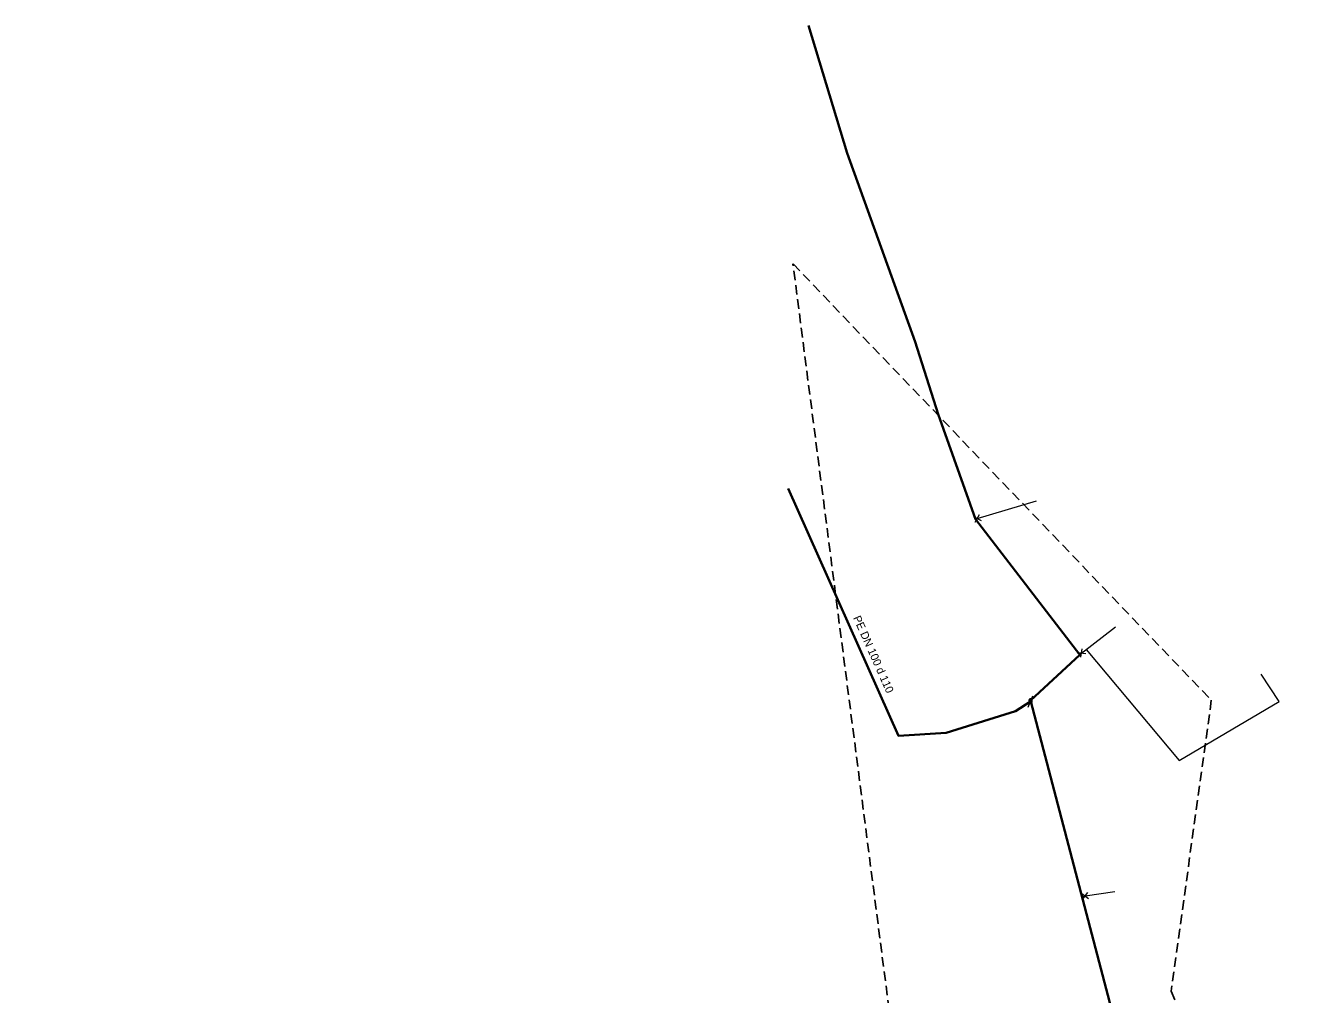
# Model space of a CAD drawing. Extents: x -743677 to -742923, y -1027084 to -1026416.
# Drawn here: x -743300.4 to -743108.7, y -1026561.5 to -1026416.4 of the extents above; entities that cross this region are included whole.
import ezdxf

# ---------------------------------------------------------------- set-up
doc = ezdxf.new("R2010")
doc.units = 0
doc.header["$LTSCALE"] = 0.48
doc.linetypes.add('MEDIUM_DASHED', pattern=[4.5, 3, -1.5])
for name, color, linetype, lineweight in [('15', 7, 'Continuous', 13), ('16', 7, 'Continuous', 35), ('59', 7, 'Continuous', 13), ('62', 7, 'MEDIUM_DASHED', 25)]:
    doc.layers.add(name, color=color, linetype=linetype, lineweight=lineweight)
doc.layers.add('17', color=7, linetype='Continuous')

msp = doc.modelspace()

# ---------------------------------------------------------------- linework, layer by layer
at = {"layer": '15'}
for p, q in [((-743158.264, -1026489.932), (-743157.131, -1026490.55)), ((-743158.008, -1026490.81), (-743157.387, -1026489.666)), ((-743142.718, -1026510.317), (-743141.438, -1026510.484)), ((-743142.162, -1026511.044), (-743141.997, -1026509.752)), ((-743150.054, -1026518.519), (-743149.357, -1026516.793)), ((-743142.045, -1026546.414), (-743141.012, -1026547.188)), ((-743141.918, -1026547.32), (-743141.14, -1026546.276))]:
    msp.add_line(p, q, dxfattribs=at)
for points in [[(-743149.495, -1026517.493), (-743149.502, -1026517.441), (-743149.519, -1026517.391), (-743149.548, -1026517.347), (-743149.585, -1026517.31), (-743149.63, -1026517.283), (-743149.679, -1026517.266), (-743149.733, -1026517.262), (-743149.784, -1026517.269), (-743149.833, -1026517.288), (-743149.877, -1026517.317), (-743149.913, -1026517.356), (-743149.939, -1026517.401), (-743149.955, -1026517.452), (-743149.958, -1026517.504), (-743149.95, -1026517.556), (-743149.929, -1026517.605), (-743149.899, -1026517.648), (-743149.86, -1026517.682), (-743149.814, -1026517.708), (-743149.762, -1026517.722), (-743149.71, -1026517.724), (-743149.659, -1026517.714), (-743149.61, -1026517.693), (-743149.568, -1026517.662), (-743149.534, -1026517.621), (-743149.51, -1026517.575), (-743149.497, -1026517.524)], [(-743149.526, -1026517.493), (-743149.532, -1026517.444), (-743149.549, -1026517.398), (-743149.576, -1026517.358), (-743149.614, -1026517.326), (-743149.657, -1026517.304), (-743149.706, -1026517.293), (-743149.755, -1026517.293), (-743149.801, -1026517.306), (-743149.845, -1026517.33), (-743149.88, -1026517.363), (-743149.907, -1026517.404), (-743149.924, -1026517.451), (-743149.928, -1026517.5), (-743149.921, -1026517.548), (-743149.902, -1026517.593), (-743149.872, -1026517.633), (-743149.833, -1026517.664), (-743149.789, -1026517.684), (-743149.742, -1026517.694), (-743149.693, -1026517.692), (-743149.646, -1026517.677), (-743149.603, -1026517.652), (-743149.568, -1026517.618), (-743149.543, -1026517.576), (-743149.529, -1026517.529)], [(-743149.458, -1026517.647), (-743149.464, -1026517.595), (-743149.481, -1026517.545), (-743149.51, -1026517.501), (-743149.547, -1026517.464), (-743149.592, -1026517.437), (-743149.642, -1026517.42), (-743149.695, -1026517.416), (-743149.747, -1026517.423), (-743149.796, -1026517.442), (-743149.839, -1026517.471), (-743149.875, -1026517.51), (-743149.901, -1026517.555), (-743149.917, -1026517.606), (-743149.92, -1026517.658), (-743149.912, -1026517.71), (-743149.892, -1026517.759), (-743149.861, -1026517.802), (-743149.822, -1026517.836), (-743149.776, -1026517.862), (-743149.725, -1026517.876), (-743149.672, -1026517.878), (-743149.621, -1026517.868), (-743149.573, -1026517.847), (-743149.53, -1026517.816), (-743149.496, -1026517.775), (-743149.472, -1026517.729), (-743149.46, -1026517.678)], [(-743149.556, -1026517.493), (-743149.561, -1026517.448), (-743149.578, -1026517.406), (-743149.607, -1026517.371), (-743149.642, -1026517.344), (-743149.684, -1026517.327), (-743149.73, -1026517.322), (-743149.774, -1026517.328), (-743149.816, -1026517.347), (-743149.85, -1026517.375), (-743149.877, -1026517.412), (-743149.894, -1026517.454), (-743149.897, -1026517.499), (-743149.891, -1026517.544), (-743149.872, -1026517.585), (-743149.843, -1026517.619), (-743149.806, -1026517.645), (-743149.762, -1026517.661), (-743149.718, -1026517.664), (-743149.673, -1026517.656), (-743149.632, -1026517.636), (-743149.598, -1026517.607), (-743149.573, -1026517.569), (-743149.559, -1026517.526)], [(-743149.488, -1026517.647), (-743149.494, -1026517.598), (-743149.511, -1026517.552), (-743149.539, -1026517.512), (-743149.576, -1026517.48), (-743149.62, -1026517.458), (-743149.668, -1026517.447), (-743149.717, -1026517.447), (-743149.764, -1026517.46), (-743149.807, -1026517.484), (-743149.843, -1026517.517), (-743149.87, -1026517.558), (-743149.886, -1026517.605), (-743149.89, -1026517.654), (-743149.883, -1026517.702), (-743149.864, -1026517.747), (-743149.834, -1026517.787), (-743149.796, -1026517.818), (-743149.752, -1026517.838), (-743149.704, -1026517.848), (-743149.655, -1026517.846), (-743149.608, -1026517.831), (-743149.565, -1026517.806), (-743149.531, -1026517.772), (-743149.505, -1026517.73), (-743149.491, -1026517.683)], [(-743149.586, -1026517.493), (-743149.59, -1026517.452), (-743149.608, -1026517.415), (-743149.636, -1026517.384), (-743149.671, -1026517.363), (-743149.711, -1026517.352), (-743149.752, -1026517.354), (-743149.791, -1026517.367), (-743149.825, -1026517.391), (-743149.85, -1026517.423), (-743149.865, -1026517.461), (-743149.867, -1026517.502), (-743149.86, -1026517.542), (-743149.84, -1026517.578), (-743149.811, -1026517.607), (-743149.774, -1026517.626), (-743149.733, -1026517.634), (-743149.693, -1026517.63), (-743149.654, -1026517.615), (-743149.622, -1026517.589), (-743149.6, -1026517.555), (-743149.587, -1026517.516)], [(-743149.518, -1026517.647), (-743149.524, -1026517.602), (-743149.541, -1026517.56), (-743149.569, -1026517.525), (-743149.605, -1026517.498), (-743149.647, -1026517.481), (-743149.692, -1026517.476), (-743149.737, -1026517.482), (-743149.778, -1026517.501), (-743149.813, -1026517.529), (-743149.84, -1026517.566), (-743149.856, -1026517.608), (-743149.86, -1026517.653), (-743149.853, -1026517.698), (-743149.834, -1026517.739), (-743149.805, -1026517.773), (-743149.768, -1026517.799), (-743149.725, -1026517.815), (-743149.68, -1026517.818), (-743149.635, -1026517.81), (-743149.595, -1026517.79), (-743149.561, -1026517.761), (-743149.535, -1026517.723), (-743149.521, -1026517.68)], [(-743149.615, -1026517.493), (-743149.62, -1026517.457), (-743149.639, -1026517.425), (-743149.664, -1026517.4), (-743149.698, -1026517.385), (-743149.735, -1026517.382), (-743149.769, -1026517.39), (-743149.801, -1026517.41), (-743149.823, -1026517.438), (-743149.837, -1026517.472), (-743149.837, -1026517.509), (-743149.826, -1026517.544), (-743149.804, -1026517.573), (-743149.774, -1026517.594), (-743149.74, -1026517.604), (-743149.703, -1026517.602), (-743149.669, -1026517.588), (-743149.642, -1026517.565), (-743149.622, -1026517.533), (-743149.615, -1026517.498)], [(-743149.548, -1026517.647), (-743149.553, -1026517.606), (-743149.571, -1026517.569), (-743149.598, -1026517.538), (-743149.633, -1026517.517), (-743149.673, -1026517.506), (-743149.714, -1026517.508), (-743149.753, -1026517.521), (-743149.787, -1026517.545), (-743149.812, -1026517.577), (-743149.827, -1026517.615), (-743149.83, -1026517.656), (-743149.822, -1026517.696), (-743149.802, -1026517.732), (-743149.773, -1026517.761), (-743149.736, -1026517.78), (-743149.696, -1026517.788), (-743149.655, -1026517.784), (-743149.617, -1026517.769), (-743149.585, -1026517.743), (-743149.562, -1026517.709), (-743149.549, -1026517.67)], [(-743149.646, -1026517.493), (-743149.651, -1026517.462), (-743149.668, -1026517.436), (-743149.693, -1026517.419), (-743149.723, -1026517.412), (-743149.755, -1026517.416), (-743149.782, -1026517.433), (-743149.799, -1026517.457), (-743149.808, -1026517.488), (-743149.804, -1026517.518), (-743149.789, -1026517.546), (-743149.764, -1026517.565), (-743149.735, -1026517.574), (-743149.703, -1026517.571), (-743149.676, -1026517.557), (-743149.656, -1026517.533), (-743149.646, -1026517.504)], [(-743149.578, -1026517.647), (-743149.583, -1026517.611), (-743149.601, -1026517.579), (-743149.627, -1026517.554), (-743149.661, -1026517.539), (-743149.697, -1026517.536), (-743149.732, -1026517.544), (-743149.763, -1026517.564), (-743149.786, -1026517.592), (-743149.799, -1026517.626), (-743149.799, -1026517.663), (-743149.788, -1026517.698), (-743149.767, -1026517.727), (-743149.737, -1026517.748), (-743149.702, -1026517.758), (-743149.665, -1026517.756), (-743149.631, -1026517.742), (-743149.604, -1026517.719), (-743149.585, -1026517.687), (-743149.578, -1026517.652)], [(-743149.676, -1026517.493), (-743149.681, -1026517.469), (-743149.698, -1026517.451), (-743149.72, -1026517.442), (-743149.745, -1026517.445), (-743149.766, -1026517.459), (-743149.777, -1026517.481), (-743149.777, -1026517.506), (-743149.764, -1026517.527), (-743149.745, -1026517.541), (-743149.72, -1026517.544), (-743149.696, -1026517.535), (-743149.681, -1026517.517)], [(-743149.608, -1026517.647), (-743149.613, -1026517.616), (-743149.63, -1026517.59), (-743149.656, -1026517.573), (-743149.686, -1026517.566), (-743149.717, -1026517.57), (-743149.744, -1026517.587), (-743149.762, -1026517.611), (-743149.77, -1026517.642), (-743149.766, -1026517.672), (-743149.751, -1026517.7), (-743149.727, -1026517.719), (-743149.697, -1026517.728), (-743149.666, -1026517.725), (-743149.638, -1026517.711), (-743149.618, -1026517.687), (-743149.608, -1026517.658)], [(-743149.706, -1026517.493), (-743149.711, -1026517.478), (-743149.725, -1026517.472), (-743149.74, -1026517.476), (-743149.747, -1026517.49), (-743149.744, -1026517.505), (-743149.73, -1026517.514), (-743149.715, -1026517.511), (-743149.706, -1026517.499)], [(-743149.638, -1026517.647), (-743149.643, -1026517.623), (-743149.66, -1026517.605), (-743149.683, -1026517.596), (-743149.707, -1026517.599), (-743149.728, -1026517.613), (-743149.739, -1026517.635), (-743149.739, -1026517.66), (-743149.727, -1026517.681), (-743149.707, -1026517.695), (-743149.682, -1026517.698), (-743149.659, -1026517.689), (-743149.643, -1026517.671)], [(-743149.668, -1026517.647), (-743149.673, -1026517.632), (-743149.688, -1026517.626), (-743149.703, -1026517.63), (-743149.71, -1026517.644), (-743149.706, -1026517.659), (-743149.693, -1026517.668), (-743149.678, -1026517.665), (-743149.668, -1026517.653)]]:
    msp.add_lwpolyline(points, close=True, dxfattribs=at)
at = {"layer": '16'}
for p, q in [((-743149.689, -1026517.647), (-743149.727, -1026517.493)), ((-743149.706, -1026517.657), (-743149.689, -1026517.647))]:
    msp.add_line(p, q, dxfattribs=at)
for points in [[(-743149.727, -1026517.493), (-743142.335, -1026510.649), (-743157.997, -1026490.35), (-743163.579, -1026474.609), (-743167.039, -1026463.78), (-743177.23, -1026435.5), (-743182.984, -1026416.403)], [(-743186.059, -1026485.73), (-743169.53, -1026522.804), (-743162.394, -1026522.381), (-743151.982, -1026519.089), (-743149.706, -1026517.657)], [(-743117.034, -1026623.984), (-743117.054, -1026623.936), (-743123.186, -1026608.25), (-743130.522, -1026587.991), (-743137.061, -1026565.84), (-743149.689, -1026517.647)]]:
    msp.add_lwpolyline(points, dxfattribs=at)
at = {"layer": '59'}
for points in [[(-743157.993, -1026490.355), (-743157.7, -1026490.24), (-743148.822, -1026487.601)], [(-743142.335, -1026510.65), (-743142.08, -1026510.4), (-743137.009, -1026506.474)], [(-743141.403, -1026509.875), (-743127.42, -1026526.487), (-743112.443, -1026517.659), (-743115.132, -1026513.588)], [(-743142.023, -1026546.904), (-743141.53, -1026546.8), (-743137.088, -1026546.149)]]:
    msp.add_lwpolyline(points, dxfattribs=at)
at = {"layer": '62'}
msp.add_lwpolyline([(-743185.331, -1026452.124), (-743185.314, -1026452.115), (-743122.624, -1026517.483), (-743128.636, -1026561.04), (-743080.591, -1026678.626), (-742988.56, -1026728.316), (-742957.099, -1026715.401), (-742922.946, -1026754.658), (-742988.389, -1026762.896), (-743109.886, -1026711.598), (-743142.114, -1026640.576), (-743238.891, -1026678.985), (-743355.253, -1026751.681), (-743402.763, -1026809.228), (-743453.197, -1026905.826), (-743482.789, -1027084.226), (-743535.862, -1027074.436), (-743492.719, -1026905.289), (-743434.421, -1026787.581), (-743381.806, -1026711.007), (-743250.543, -1026637.895), (-743166.228, -1026600.23)], close=True, dxfattribs=at)

# ---------------------------------------------------------------- texts
at = {"layer": '17'}
msp.add_text('PE DN 100 d 110 ', height=1.2, rotation=294, dxfattribs=at).set_placement((-743176.351, -1026505.128))

doc.saveas('drawing.dxf')
